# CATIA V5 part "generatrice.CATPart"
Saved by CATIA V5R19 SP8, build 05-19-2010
Part number: generatrice
Bounding box of the stored display mesh (mm): x -59.975 to 59.975, y -380 to 0, z -59.975 to 59.975
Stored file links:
  G:\EU_thinkMotion\CFAO_2010\MMS_groupe2\MMS_groupe2\A reprendre\splanchenault\Planchenault\generatrice.CATPart
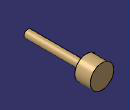
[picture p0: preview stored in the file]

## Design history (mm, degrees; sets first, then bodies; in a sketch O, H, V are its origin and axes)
Body1 (main body)
  Sketch1 on yz-plane, origin (0, 0, 0), H (0, 1, 0), V (0, 0, 1)
    line L1 (0, 0) -> (0, -60)
    line L2 (0, -60) -> (-80, -60)
    line L3 (-80, -60) -> (-80, -20)
    line L4 (-80, -20) -> (-380, -20)
    line L5 (-380, -20) -> (-380, 0)
    line L6 (-380, 0) -> (0, 0)
    length L1 = 60
    length L2 = 80
    length L6 = 380
    length L3 = 40
    vertical: L1 V, L3 V, L5 V
    horizontal: L2 H, L4 H, L6 H
  Shaft1: profile Sketch1, axis Sketch1.L6, angle 360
